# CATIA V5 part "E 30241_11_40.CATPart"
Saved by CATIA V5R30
Part number: Zarazka
Definition: E 30241_11_40
Nomenclature: E 30241_11_40
Source: Unknown
Description: PART-E 30241_11_40-DESC
Bounding box of the stored display mesh (mm): x -18 to 0, y -11 to 5, z -20 to 20
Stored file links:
  E:\Bakalarka\Model\Forma_v7\E 30241_11_40.CATPart
  E:\Bakalarka\Model\Forma_v7\Zarazka_slideru.CATProduct
  Forma_Zarazka_slideru.CATPart
  E:\Bakalarka\Model\Chyba catie 2\Slider_1_Zarazka_slideru.CATPart
  E:\Bakalarka\Model\Chyba catie 2\Slider_1_Zarazka_slideru_1.CATPart
  E:\Bakalarka\Model\Forma_v7\Slider_1_Zarazka_slideru_2.CATPart
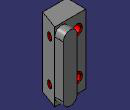
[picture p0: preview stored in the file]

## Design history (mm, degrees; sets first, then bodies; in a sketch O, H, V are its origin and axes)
Set1
  Sketch1 on face of Solid1, origin (0, -11, 0), H (1, 0, 0), V (0, 0, 1)
    reference projected arc E2 centre (-13, -12) radius 4 from (-17, -12) to (-9, -12) ccw from edge [face of Solid1 | face of Solid1]
    reference projected arc E4 centre (-13, 12) radius 4 from (-17, 12) to (-9, 12) ccw from edge [face of Solid1 | face of Solid1]
    point P9 (-13, 12)
    point P10 (-13, -12)
    concentricity: P9 E4, P10 E2
Body1 "MANIFOLD_SOLID_BREP #197" (main body)
  Solid1: solid without history
  DatumCurve1 to DatumCurve4
  Sketch2 on face of Solid1, origin (0, -11, 0), H (1, 0, 0), V (0, 0, 1)
  Body2 "Result of DrillHole"
    Solid2: linked copy from another document
  Assemble1 "DrillHoleCapScrew_E1200_4.1": tool Body2
  Body3 "Result of DrillHole"
    Solid3: linked copy from another document
  Assemble2 "DrillHoleCapScrew_E1200_4.2": tool Body3
  Body4 "Result of DrillHole"
    Solid4: linked copy from another document
  Assemble3 "DrillHoleCapScrew_E1200_2.1": tool Body4
  Body5 "Result of DrillHole"
    Solid5: linked copy from another document
  Assemble4 "DrillHoleCapScrew_E1200_2.2": tool Body5
  Body6 "Result of DrillHole"
    Solid6: linked copy from another document
  Assemble5 "DrillHoleCapScrew_E1200_1.1": tool Body6
  Body7 "Result of DrillHole"
    Solid7: linked copy from another document
  Assemble6 "DrillHoleCapScrew_E1200_1.2": tool Body7
  Body8 "Result of DrillHole"
    Solid8: linked copy from another document
  Assemble7 "DrillHoleCapScrew_E1200_2.3": tool Body8
  Body9 "Result of DrillHole"
    Solid9: linked copy from another document
  Assemble8 "DrillHoleCapScrew_E1200_2.4": tool Body9
  Sketch3 on face of Solid1, origin (0, -11, 0), H (1, 0, 0), V (0, 0, 1)
    reference projected circle E1 centre (-13, 12) radius 4 from edge [face of Solid1 | face of Solid1]
    reference projected circle E2 centre (-13, -12) radius 4 from edge [face of Solid1 | face of Solid1]
    point P1 (-13, 12)
    point P2 (-13, -12)
    concentricity: P1 E1, P2 E2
